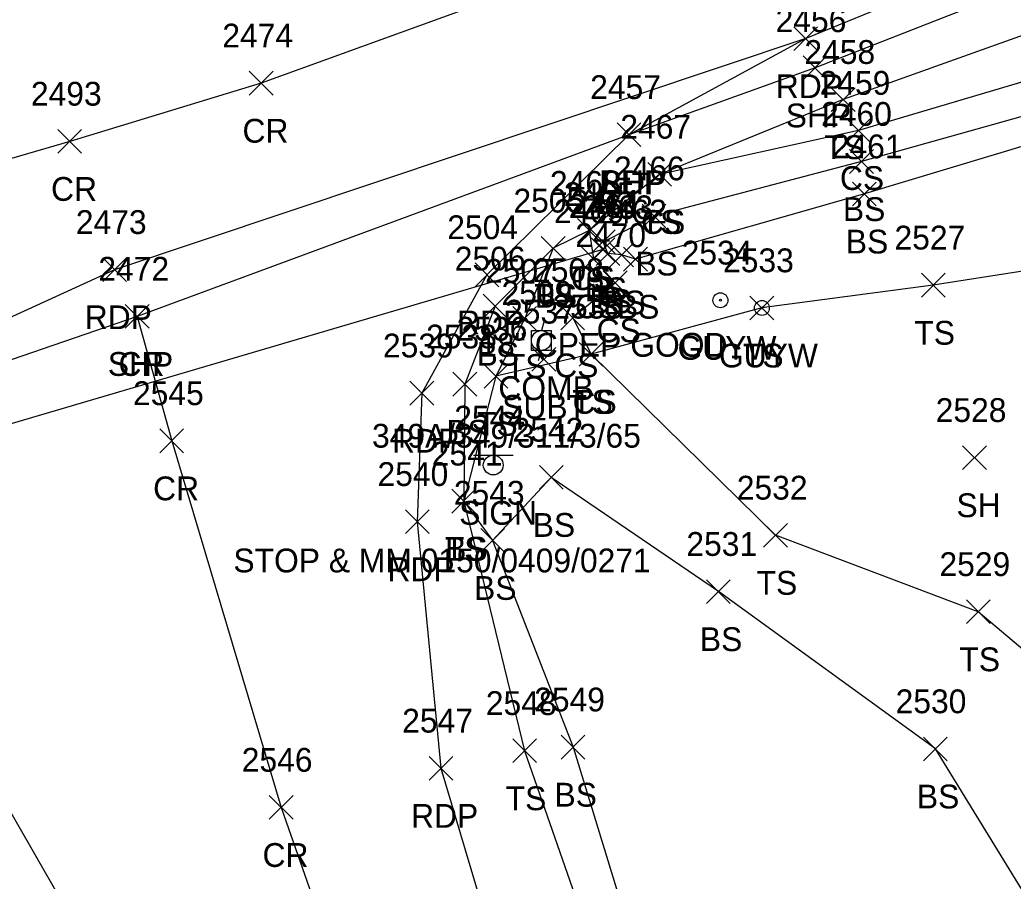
# Model space of a CAD drawing. Extents: x 1520648 to 1523413, y 732854 to 735518.
# Drawn here: x 1521837.4 to 1521920.9, y 733639.3 to 733711.6 of the extents above; entities that cross this region are included whole.
import ezdxf

# ---------------------------------------------------------------- set-up
doc = ezdxf.new("R2010")
doc.units = 0
for name, color, linetype in [('D_A', 7, 'Continuous'), ('D_C', 7, 'Continuous'), ('D_I', 7, 'Continuous'), ('D_TIC', 7, 'Continuous'), ('DCP', 7, 'Continuous'), ('L_A', 7, 'Continuous'), ('L_I', 7, 'Continuous'), ('L_TIC', 7, 'Continuous'), ('LELB', 7, 'Continuous'), ('P_A', 7, 'Continuous'), ('P_I', 7, 'Continuous'), ('P_TIC', 7, 'Continuous'), ('PET', 7, 'Continuous'), ('PRC', 7, 'Continuous'), ('PSP', 7, 'Continuous'), ('S_A', 7, 'Continuous'), ('S_C', 7, 'Continuous'), ('S_I', 7, 'Continuous'), ('SSGN', 7, 'Continuous'), ('U_A', 7, 'Continuous'), ('U_C', 7, 'Continuous'), ('U_I', 7, 'Continuous'), ('U_TIC', 7, 'Continuous'), ('UP', 7, 'Continuous'), ('UPGW', 7, 'Continuous')]:
    doc.layers.add(name, color=color, linetype=linetype)

msp = doc.modelspace()

# ---------------------------------------------------------------- linework, layer by layer
at = {"layer": 'D_TIC'}
for points in [[(1521885.452, 733691.333), (1521887.452, 733693.333)], [(1521887.452, 733691.333), (1521885.452, 733693.333)]]:
    msp.add_lwpolyline(points, dxfattribs=at)
at = {"layer": 'DCP'}
msp.add_lwpolyline([(1521886.452, 733692.333), (1521807.841, 733669.192)], dxfattribs=at)
at = {"layer": 'L_TIC'}
for points in [[(1521905.643, 733703.941), (1521907.643, 733705.941)], [(1521907.643, 733703.941), (1521905.643, 733705.941)], [(1521906.93, 733701.346), (1521908.93, 733703.346)], [(1521908.93, 733701.346), (1521906.93, 733703.346)], [(1521907.181, 733698.737), (1521909.181, 733700.737)], [(1521909.181, 733698.737), (1521907.181, 733700.737)], [(1521890.214, 733697.657), (1521892.214, 733699.657)], [(1521892.214, 733697.657), (1521890.214, 733699.657)], [(1521890.214, 733697.657), (1521892.214, 733699.657)], [(1521892.214, 733697.657), (1521890.214, 733699.657)], [(1521907.425, 733696.009), (1521909.425, 733698.009)], [(1521909.425, 733696.009), (1521907.425, 733698.009)], [(1521889.734, 733694.159), (1521891.734, 733696.159)], [(1521891.734, 733694.159), (1521889.734, 733696.159)], [(1521889.734, 733694.159), (1521891.734, 733696.159)], [(1521891.734, 733694.159), (1521889.734, 733696.159)], [(1521884.295, 733692.938), (1521886.295, 733694.938)], [(1521886.295, 733692.938), (1521884.295, 733694.938)], [(1521884.295, 733692.938), (1521886.295, 733694.938)], [(1521886.295, 733692.938), (1521884.295, 733694.938)], [(1521881.263, 733691.448), (1521883.263, 733693.448)], [(1521883.263, 733691.448), (1521881.263, 733693.448)], [(1521881.263, 733691.448), (1521883.263, 733693.448)], [(1521883.263, 733691.448), (1521881.263, 733693.448)], [(1521885.465, 733691.996), (1521887.465, 733693.996)], [(1521887.465, 733691.996), (1521885.465, 733693.996)], [(1521884.647, 733690.56), (1521886.647, 733692.56)], [(1521886.647, 733690.56), (1521884.647, 733692.56)], [(1521885.87, 733690.994), (1521887.87, 733692.994)], [(1521887.87, 733690.994), (1521885.87, 733692.994)], [(1521887.015, 733690.887), (1521889.015, 733692.887)], [(1521889.015, 733690.887), (1521887.015, 733692.887)], [(1521888.183, 733690.532), (1521890.183, 733692.532)], [(1521890.183, 733690.532), (1521888.183, 733692.532)], [(1521886.471, 733688.545), (1521888.471, 733690.545)], [(1521888.471, 733688.545), (1521886.471, 733690.545)], [(1521913.217, 733688.344), (1521915.217, 733690.344)], [(1521915.217, 733688.344), (1521913.217, 733690.344)], [(1521876.384, 733686.579), (1521878.384, 733688.579)], [(1521878.384, 733686.579), (1521876.384, 733688.579)], [(1521898.807, 733686.433), (1521900.807, 733688.433)], [(1521900.807, 733686.433), (1521898.807, 733688.433)], [(1521878.875, 733685.549), (1521880.875, 733687.549)], [(1521880.875, 733685.549), (1521878.875, 733687.549)], [(1521882.909, 733685.602), (1521884.909, 733687.602)], [(1521884.909, 733685.602), (1521882.909, 733687.602)], [(1521884.45, 733682.539), (1521886.45, 733684.539)], [(1521886.45, 733682.539), (1521884.45, 733684.539)], [(1521884.45, 733682.539), (1521886.45, 733684.539)], [(1521886.45, 733682.539), (1521884.45, 733684.539)], [(1521884.45, 733682.539), (1521886.45, 733684.539)], [(1521886.45, 733682.539), (1521884.45, 733684.539)], [(1521876.455, 733680.686), (1521878.455, 733682.686)], [(1521878.455, 733680.686), (1521876.455, 733682.686)], [(1521876.455, 733680.686), (1521878.455, 733682.686)], [(1521878.455, 733680.686), (1521876.455, 733682.686)], [(1521873.837, 733680.027), (1521875.837, 733682.027)], [(1521875.837, 733680.027), (1521873.837, 733682.027)], [(1521916.681, 733673.849), (1521918.681, 733675.849)], [(1521918.681, 733673.849), (1521916.681, 733675.849)], [(1521881.104, 733672.194), (1521883.104, 733674.194)], [(1521883.104, 733672.194), (1521881.104, 733674.194)], [(1521873.746, 733670.189), (1521875.746, 733672.189)], [(1521875.746, 733670.189), (1521873.746, 733672.189)], [(1521873.746, 733670.189), (1521875.746, 733672.189)], [(1521875.746, 733670.189), (1521873.746, 733672.189)], [(1521899.959, 733667.325), (1521901.959, 733669.325)], [(1521901.959, 733667.325), (1521899.959, 733669.325)], [(1521876.172, 733666.899), (1521878.172, 733668.899)], [(1521878.172, 733666.899), (1521876.172, 733668.899)], [(1521876.172, 733666.899), (1521878.172, 733668.899)], [(1521878.172, 733666.899), (1521876.172, 733668.899)], [(1521895.155, 733662.594), (1521897.155, 733664.594)], [(1521897.155, 733662.594), (1521895.155, 733664.594)], [(1521917.005, 733660.9), (1521919.005, 733662.9)], [(1521919.005, 733660.9), (1521917.005, 733662.9)], [(1521878.861, 733649.221), (1521880.861, 733651.221)], [(1521880.861, 733649.221), (1521878.861, 733651.221)], [(1521882.934, 733649.522), (1521884.934, 733651.522)], [(1521884.934, 733649.522), (1521882.934, 733651.522)], [(1521913.4, 733649.371), (1521915.4, 733651.371)], [(1521915.4, 733649.371), (1521913.4, 733651.371)]]:
    msp.add_lwpolyline(points, dxfattribs=at)
at = {"layer": 'LELB'}
for points in [[(1522137.237, 733813.36), (1522122.604, 733811.135), (1522114.406, 733809.375), (1522103.706, 733801.783), (1522081.649, 733783.392), (1522057.761, 733761.392), (1522025.51, 733740.121), (1522002.626, 733729.985), (1521968.836, 733727.782), (1521950.734, 733720.718), (1521906.643, 733704.941), (1521891.214, 733698.657), (1521885.295, 733693.938), (1521882.263, 733692.448), (1521879.875, 733686.549), (1521877.455, 733681.686), (1521874.746, 733671.189), (1521879.861, 733650.221), (1521887.887, 733627.143), (1521900.413, 733584.463), (1521909.701, 733557.243), (1521917.258, 733535.261)], [(1522120.862, 733803.477), (1522117.747, 733806.817), (1522113.051, 733804.251), (1522109.473, 733798.617), (1522083.975, 733778.274), (1522063.262, 733752.213), (1522037.469, 733737.801), (1522005.964, 733725.806), (1521972.134, 733723.953), (1521953.539, 733715.885), (1521907.93, 733702.346), (1521891.214, 733698.657)], [(1522023.756, 733721.952), (1522019.284, 733725.704), (1522008.74, 733719.105), (1521974.346, 733719.006), (1521953.678, 733712.487), (1521908.181, 733699.737), (1521890.734, 733695.159)], [(1521954.362, 733710.845), (1521908.425, 733697.009), (1521889.183, 733691.532), (1521888.015, 733691.887), (1521886.87, 733691.994), (1521886.465, 733692.996), (1521890.734, 733695.159)], [(1521955.95, 733701.456), (1521931.258, 733692.005), (1521914.217, 733689.344), (1521899.807, 733687.433), (1521885.45, 733683.539), (1521877.455, 733681.686)], [(1521885.295, 733693.938), (1521885.647, 733691.56), (1521887.471, 733689.545), (1521883.909, 733686.602), (1521885.45, 733683.539)], [(1521882.263, 733692.448), (1521877.384, 733687.579), (1521874.837, 733681.027), (1521874.746, 733671.189), (1521877.172, 733667.899), (1521883.934, 733650.522), (1521891.132, 733627.078), (1521905.053, 733586.166), (1521916.398, 733559.51)], [(1521963.108, 733617.364), (1521959.229, 733611.531), (1521944.122, 733624.476), (1521938.133, 733644.921), (1521918.005, 733661.9), (1521900.959, 733668.325), (1521885.45, 733683.539)], [(1521945.534, 733595.31), (1521935.038, 733616.792), (1521914.4, 733650.371), (1521896.155, 733663.594), (1521882.104, 733673.194), (1521877.172, 733667.899)]]:
    msp.add_lwpolyline(points, dxfattribs=at)
at = {"layer": 'P_TIC'}
for points in [[(1521902.494, 733709.068), (1521904.494, 733711.068)], [(1521904.494, 733709.068), (1521902.494, 733711.068)], [(1521902.494, 733709.068), (1521904.494, 733711.068)], [(1521904.494, 733709.068), (1521902.494, 733711.068)], [(1521903.277, 733706.61), (1521905.277, 733708.61)], [(1521905.277, 733706.61), (1521903.277, 733708.61)], [(1521856.71, 733705.322), (1521858.71, 733707.322)], [(1521858.71, 733705.322), (1521856.71, 733707.322)], [(1521887.633, 733700.989), (1521889.633, 733702.989)], [(1521889.633, 733700.989), (1521887.633, 733702.989)], [(1521887.633, 733700.989), (1521889.633, 733702.989)], [(1521889.633, 733700.989), (1521887.633, 733702.989)], [(1521840.616, 733700.433), (1521842.616, 733702.433)], [(1521842.616, 733700.433), (1521840.616, 733702.433)], [(1521844.394, 733689.649), (1521846.394, 733691.649)], [(1521846.394, 733689.649), (1521844.394, 733691.649)], [(1521875.697, 733689.213), (1521877.697, 733691.213)], [(1521877.697, 733689.213), (1521875.697, 733691.213)], [(1521846.287, 733685.723), (1521848.287, 733687.723)], [(1521848.287, 733685.723), (1521846.287, 733687.723)], [(1521846.287, 733685.723), (1521848.287, 733687.723)], [(1521848.287, 733685.723), (1521846.287, 733687.723)], [(1521870.222, 733679.273), (1521872.222, 733681.273)], [(1521872.222, 733679.273), (1521870.222, 733681.273)], [(1521849.198, 733675.267), (1521851.198, 733677.267)], [(1521851.198, 733675.267), (1521849.198, 733677.267)], [(1521869.841, 733668.469), (1521871.841, 733670.469)], [(1521871.841, 733668.469), (1521869.841, 733670.469)], [(1521871.828, 733647.743), (1521873.828, 733649.743)], [(1521873.828, 733647.743), (1521871.828, 733649.743)], [(1521858.396, 733644.455), (1521860.396, 733646.455)], [(1521860.396, 733644.455), (1521858.396, 733646.455)]]:
    msp.add_lwpolyline(points, dxfattribs=at)
at = {"layer": 'PET'}
for points in [[(1522293.194, 733992.175), (1522263.712, 733955.946), (1522232.455, 733921.589), (1522205.93, 733894.992), (1522171.676, 733864.451), (1522150.755, 733846.951), (1522111.89, 733818.73), (1522077.257, 733795.558), (1522046.35, 733777.345), (1522014.71, 733760.043), (1521992.386, 733748.515), (1521963.746, 733735.045), (1521947.246, 733727.941), (1521903.494, 733710.068), (1521845.394, 733690.649), (1521824.845, 733681.254), (1521803.807, 733674.865), (1521790.983, 733674.845), (1521764.049, 733667.923), (1521729.464, 733658.425), (1521691.158, 733648.143)], [(1521903.494, 733710.068), (1521888.633, 733701.989), (1521876.697, 733690.213), (1521871.222, 733680.273), (1521870.841, 733669.469), (1521872.828, 733648.743), (1521880.313, 733623.661), (1521893.14, 733582.118), (1521902.797, 733554.605), (1521915.131, 733524.472)], [(1521970.761, 732869.717), (1521972.093, 732922.911), (1521973.567, 732966.674), (1521974.582, 733022.365), (1521975.455, 733067.379), (1521975.322, 733107.575), (1521973.636, 733153.168), (1521968.72, 733197.531), (1521962.948, 733241.685), (1521954.955, 733285.149), (1521946.266, 733327.15), (1521938.01, 733358.791), (1521928.179, 733397.898), (1521917.022, 733438.97), (1521903.82, 733481.125), (1521892.952, 733514.594), (1521880.752, 733548.749), (1521865.844, 733587.223), (1521849.85, 733622.069), (1521833.37, 733650.777), (1521822.9, 733665.592), (1521814.387, 733670.773), (1521809.288, 733673.666), (1521803.807, 733674.865)]]:
    msp.add_lwpolyline(points, dxfattribs=at)
at = {"layer": 'PRC'}
for points in [[(1522254.708, 733962.62), (1522224.204, 733928.998), (1522197.911, 733902.998), (1522164.255, 733873.016), (1522142.54, 733855.168), (1522104.412, 733827.43), (1522070.845, 733804.697), (1522039.569, 733786.252), (1522009.598, 733770.035), (1521986.99, 733758.562), (1521958.12, 733745.427), (1521942.227, 733738.37), (1521896.324, 733720.332), (1521857.71, 733706.322), (1521841.616, 733701.433), (1521812.172, 733692.842), (1521787.027, 733685.658), (1521768.249, 733680.623), (1521726.089, 733669.372), (1521688.171, 733658.559)], [(1521847.287, 733686.723), (1521850.198, 733676.267), (1521859.396, 733645.455), (1521868.491, 733619.427), (1521882.711, 733578.348), (1521892.299, 733552.113), (1521903.284, 733519.937), (1521912.826, 733491.675), (1521925.085, 733452.23), (1521933.203, 733423.68), (1521950.731, 733358.33), (1521960.471, 733313.717), (1521967.865, 733278.36), (1521975.829, 733229.911), (1521982.148, 733180.3), (1521985.067, 733144.213), (1521986.34, 733103.302), (1521986.874, 733068.499), (1521985.991, 733025.535), (1521985.59, 732997.694), (1521984.107, 732947.622), (1521983.042, 732898.649), (1521981.541, 732858.939)]]:
    msp.add_lwpolyline(points, dxfattribs=at)
at = {"layer": 'PSP'}
msp.add_lwpolyline([(1522408.205, 734139.279), (1522381.044, 734102.475), (1522353.021, 734064.874), (1522324.006, 734025.281), (1522296.174, 733989.549), (1522266.628, 733953.31), (1522235.292, 733918.787), (1522209.781, 733890.984), (1522201.901, 733884.12), (1522173.488, 733859.111), (1522154.026, 733843.415), (1522113.548, 733816.073), (1522079.344, 733793.188), (1522048.296, 733774.459), (1522016.588, 733757.423), (1521993.944, 733745.829), (1521965.161, 733732.44), (1521948.662, 733724.972), (1521904.277, 733707.61), (1521888.633, 733701.989), (1521847.287, 733686.723), (1521809.288, 733673.666)], dxfattribs=at)
at = {"layer": 'SSGN'}
for p, q in [((1521875.578, 733675.063), (1521878.911, 733675.063)), ((1521877.224, 733674.229), (1521877.224, 733674.229))]:
    msp.add_line(p, q, dxfattribs=at)
msp.add_circle((1521877.224, 733674.229), 0.833, dxfattribs=at)
at = {"layer": 'U_TIC'}
for points in [[(1521880.481, 733682.118), (1521882.481, 733684.118)], [(1521882.481, 733682.118), (1521880.481, 733684.118)]]:
    msp.add_lwpolyline(points, dxfattribs=at)
at = {"layer": 'UP'}
for p, q in [((1521881.518, 733686.359), (1521881.268, 733685.525)), ((1521880.435, 733683.859), (1521880.435, 733685.525)), ((1521880.435, 733685.525), (1521882.102, 733685.525)), ((1521882.102, 733685.525), (1521882.102, 733683.859)), ((1521881.268, 733684.692), (1521881.268, 733684.692)), ((1521882.102, 733683.859), (1521880.435, 733683.859)), ((1521881.018, 733683.025), (1521881.268, 733683.859))]:
    msp.add_line(p, q, dxfattribs=at)
msp.add_circle((1521881.268, 733684.692), 0.833, dxfattribs=at)
at = {"layer": 'UPGW'}
for centre, radius in [((1521896.324, 733688.079), 0.625), ((1521896.324, 733688.079), 0.0833), ((1521899.807, 733687.433), 0.625), ((1521899.807, 733687.433), 0.0833)]:
    msp.add_circle(centre, radius, dxfattribs=at)

# ---------------------------------------------------------------- texts
at = {"layer": 'D_A'}
msp.add_text('P', height=2, dxfattribs=at).set_placement((1521885.83, 733687.333))
at = {"layer": 'D_C'}
msp.add_text('18" CPEP GOOD', height=2, dxfattribs=at).set_placement((1521876.05, 733683.333))
at = {"layer": 'D_I'}
msp.add_text('2471', height=2, dxfattribs=at).set_placement((1521883.759, 733695.333))
at = {"layer": 'L_A'}
for s, p in [('TS', (1521905.053, 733699.941)), ('CS', (1521906.371, 733697.346)), ('BS', (1521906.622, 733694.737)), ('TS', (1521889.624, 733693.657)), ('CS', (1521889.655, 733693.657)), ('BS', (1521906.866, 733692.009)), ('BS', (1521889.175, 733690.159)), ('BS', (1521889.175, 733690.159)), ('TS', (1521883.704, 733688.938)), ('CS', (1521883.736, 733688.938)), ('BS', (1521884.906, 733687.996)), ('TS', (1521880.673, 733687.448)), ('BS', (1521880.704, 733687.448)), ('CS', (1521884.088, 733686.56)), ('BS', (1521885.311, 733686.994)), ('BS', (1521886.456, 733686.887)), ('BS', (1521887.624, 733686.532)), ('CS', (1521885.912, 733684.545)), ('TS', (1521912.627, 733684.344)), ('BS', (1521875.825, 733682.579)), ('TS', (1521898.217, 733682.433)), ('TS', (1521878.285, 733681.549)), ('CS', (1521882.35, 733681.602)), ('TS', (1521883.86, 733678.539)), ('TS', (1521883.86, 733678.539)), ('CS', (1521883.891, 733678.539)), ('TS', (1521875.864, 733676.686)), ('TS', (1521875.864, 733676.686)), ('BS', (1521873.278, 733676.027)), ('SH', (1521916.169, 733669.849)), ('BS', (1521880.545, 733668.194)), ('TS', (1521873.155, 733666.189)), ('BS', (1521873.187, 733666.189)), ('BS', (1521875.613, 733662.899)), ('BS', (1521875.613, 733662.899)), ('TS', (1521899.369, 733663.325)), ('BS', (1521894.595, 733658.594)), ('TS', (1521916.415, 733656.9)), ('BS', (1521882.375, 733645.522)), ('BS', (1521912.841, 733645.371)), ('TS', (1521878.27, 733645.221))]:
    msp.add_text(s, height=2, dxfattribs=at).set_placement(p)
at = {"layer": 'L_I'}
for s, p in [('2458', (1521903.383, 733707.941)), ('2459', (1521904.662, 733705.346)), ('2460', (1521904.787, 733702.737)), ('2467', (1521887.907, 733701.657)), ('2467', (1521887.907, 733701.657)), ('2461', (1521905.685, 733700.009)), ('2466', (1521887.372, 733698.159)), ('2466', (1521887.372, 733698.159)), ('2468', (1521881.988, 733696.938)), ('2468', (1521881.988, 733696.938)), ('2505', (1521878.925, 733695.448)), ('2505', (1521878.925, 733695.448)), ('2465', (1521883.158, 733695.996)), ('2464', (1521883.563, 733694.994)), ('2463', (1521884.708, 733694.887)), ('2469', (1521882.332, 733694.56)), ('2462', (1521885.876, 733694.532)), ('2470', (1521884.124, 733692.545)), ('2527', (1521910.958, 733692.344)), ('2506', (1521873.99, 733690.579)), ('2533', (1521896.547, 733690.433)), ('2508', (1521880.571, 733689.602)), ('2507', (1521876.536, 733689.549)), ('2535', (1521882.19, 733686.539)), ('2535', (1521882.19, 733686.539)), ('2535', (1521882.19, 733686.539)), ('2536', (1521874.14, 733684.686)), ('2536', (1521874.14, 733684.686)), ('2538', (1521871.577, 733684.027)), ('2528', (1521914.421, 733677.849)), ('2542', (1521878.844, 733676.194)), ('2541', (1521872.053, 733674.189)), ('2541', (1521872.053, 733674.189)), ('2532', (1521897.7, 733671.325)), ('2543', (1521873.912, 733670.899)), ('2543', (1521873.912, 733670.899)), ('2531', (1521893.462, 733666.594)), ('2529', (1521914.738, 733664.9)), ('2548', (1521876.601, 733653.221)), ('2549', (1521880.666, 733653.522)), ('2530', (1521911.053, 733653.371))]:
    msp.add_text(s, height=2, dxfattribs=at).set_placement(p)
at = {"layer": 'P_A'}
for s, p in [('RDP', (1521900.982, 733705.068)), ('RDP', (1521900.982, 733705.068)), ('SHP', (1521901.812, 733702.61)), ('CR', (1521856.143, 733701.322)), ('CR', (1521840.049, 733696.433)), ('SHP', (1521886.168, 733696.989)), ('RDP', (1521886.121, 733696.989)), ('RDP', (1521842.882, 733685.649)), ('RDP', (1521874.185, 733685.213)), ('SHP', (1521844.822, 733681.723)), ('CR', (1521845.72, 733681.723)), ('RDP', (1521868.71, 733675.273)), ('CR', (1521848.631, 733671.267)), ('RDP', (1521868.329, 733664.469)), ('RDP', (1521870.316, 733643.743)), ('CR', (1521857.829, 733640.455))]:
    msp.add_text(s, height=2, dxfattribs=at).set_placement(p)
at = {"layer": 'P_I'}
for s, p in [('2456', (1521900.962, 733710.61)), ('2474', (1521854.45, 733709.322)), ('2457', (1521885.373, 733704.989)), ('2457', (1521885.373, 733704.989)), ('2493', (1521838.357, 733704.433)), ('2473', (1521842.134, 733693.649)), ('2504', (1521873.358, 733693.213)), ('2472', (1521844.027, 733689.723)), ('2472', (1521844.027, 733689.723)), ('2539', (1521867.954, 733683.273)), ('2545', (1521846.939, 733679.267)), ('2540', (1521867.494, 733672.469)), ('2547', (1521869.568, 733651.743)), ('2546', (1521856.081, 733648.455))]:
    msp.add_text(s, height=2, dxfattribs=at).set_placement(p)
at = {"layer": 'S_A'}
msp.add_text('SIGN', height=2, dxfattribs=at).set_placement((1521874.362, 733669.209))
at = {"layer": 'S_C'}
msp.add_text('STOP & MM 0150/0409/0271', height=2, dxfattribs=at).set_placement((1521855.378, 733665.209))
at = {"layer": 'S_I'}
msp.add_text('2544', height=2, dxfattribs=at).set_placement((1521873.945, 733677.209))
at = {"layer": 'U_A'}
for s, p in [('GUYW', (1521892.718, 733683.079)), ('GUYW', (1521896.201, 733682.433)), ('COMB', (1521877.654, 733679.692)), ('SUBT', (1521877.977, 733678.118))]:
    msp.add_text(s, height=2, dxfattribs=at).set_placement(p)
at = {"layer": 'U_C'}
msp.add_text('349A/349/311/3/65', height=2, dxfattribs=at).set_placement((1521867.032, 733675.692))
at = {"layer": 'U_I'}
for s, p in [('2534', (1521893.064, 733691.079)), ('2533', (1521896.547, 733690.433)), ('2509', (1521877.922, 733687.692)), ('2537', (1521878.222, 733686.118))]:
    msp.add_text(s, height=2, dxfattribs=at).set_placement(p)

doc.saveas('drawing.dxf')
